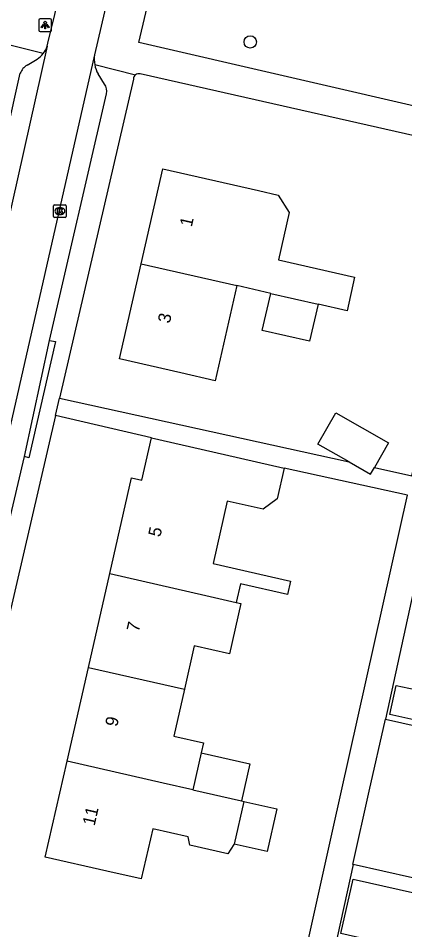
# Model space of a CAD drawing. Extents: x 163686 to 164493, y 382719 to 383870.
# Drawn here: x 164007.2 to 164037.9, y 383506.8 to 383579.1 of the extents above; entities that cross this region are included whole.
import ezdxf

# ---------------------------------------------------------------- set-up
doc = ezdxf.new("R2010")
doc.units = 0
for name, color, linetype in [('IMGEO_Boom', 7, 'Continuous'), ('IMGEO_Kolk', 7, 'Continuous'), ('IMGEO_Lichtpunt', 7, 'Continuous'), ('IMGEO_Pand', 7, 'Continuous'), ('IMGEO_Pand_nummerreeks', 7, 'Continuous'), ('IMGEO_Rijbaan_lokaal_open', 7, 'Continuous'), ('IMGEO_Voetpad_open', 7, 'Continuous')]:
    doc.layers.add(name, color=color, linetype=linetype)

msp = doc.modelspace()

# ---------------------------------------------------------------- linework, layer by layer
at = {"layer": 'IMGEO_Boom'}
msp.add_circle((164025.64, 383577.233), 0.489, dxfattribs=at)
at = {"layer": 'IMGEO_Kolk'}
for p, q in [((164010.039, 383563.39), (164010.039, 383564.242)), ((164010.114, 383564.316), (164010.966, 383564.316)), ((164010.527, 383564.096), (164010.552, 383564.096)), ((164011.04, 383564.242), (164011.04, 383563.39)), ((164010.966, 383563.316), (164010.114, 383563.316)), ((164010.55, 383563.536), (164010.525, 383563.536))]:
    msp.add_line(p, q, dxfattribs=at)
for points in [[(164010.039, 383563.39), (164010.039, 383564.242)], [(164010.114, 383564.316), (164010.966, 383564.316)], [(164010.36, 383564.016), (164010.483, 383564.016), (164010.483, 383563.865), (164010.613, 383564.016), (164010.777, 383564.016), (164010.631, 383563.865), (164010.784, 383563.616), (164010.632, 383563.616), (164010.547, 383563.78), (164010.483, 383563.713), (164010.483, 383563.616), (164010.36, 383563.616), (164010.36, 383564.016)], [(164011.04, 383564.242), (164011.04, 383563.39)], [(164010.966, 383563.316), (164010.114, 383563.316)]]:
    msp.add_lwpolyline(points, dxfattribs=at)
for centre, start, end in [((164010.116, 383564.24), 91.55205, 178.44795), ((164010.116, 383564.24), 91.55205, 178.44795), ((164010.964, 383564.24), 1.55205, 88.44795), ((164010.964, 383564.24), 1.55205, 88.44795), ((164010.116, 383563.392), 181.55205, 268.44795), ((164010.116, 383563.392), 181.55205, 268.44795), ((164010.964, 383563.392), 271.55205, 358.44795), ((164010.964, 383563.392), 271.55205, 358.44795)]:
    msp.add_arc(centre, 0.0765, start, end, dxfattribs=at)
for centre, major_axis, ratio, start_param, end_param in [((164010.526, 383563.816), (-0.387, 0.002), 0.722429, 4.712389, 7.853982), ((164010.551, 383563.816), (-0.39, 0.002), 0.717154, 1.570796, 4.712389)]:
    msp.add_ellipse(centre, major_axis=major_axis, ratio=ratio, start_param=start_param, end_param=end_param, dxfattribs=at)
at = {"layer": 'IMGEO_Lichtpunt'}
for p, q in [((164009.773, 383579.07), (164008.965, 383579.07)), ((164009.773, 383579.07), (164008.965, 383579.07)), ((164008.871, 383578.975), (164008.871, 383578.168)), ((164008.871, 383578.975), (164008.871, 383578.168)), ((164009.867, 383578.168), (164009.867, 383578.975)), ((164009.867, 383578.168), (164009.867, 383578.975)), ((164008.965, 383578.074), (164009.773, 383578.074)), ((164008.965, 383578.074), (164009.773, 383578.074))]:
    msp.add_line(p, q, dxfattribs=at)
for points in [[(164009.245, 383578.639), (164009.284, 383578.611), (164009.096, 383578.349), (164009.058, 383578.376), (164009.245, 383578.639)], [(164009.347, 383578.591), (164009.394, 383578.591), (164009.394, 383578.269), (164009.347, 383578.269), (164009.347, 383578.591)], [(164009.457, 383578.611), (164009.495, 383578.638), (164009.682, 383578.376), (164009.643, 383578.348), (164009.457, 383578.611)]]:
    msp.add_lwpolyline(points, dxfattribs=at)
msp.add_circle((164009.37, 383578.773), 0.0994, dxfattribs=at)
for centre, start, end in [((164008.965, 383578.975), 90, 180), ((164008.965, 383578.975), 90, 180), ((164009.773, 383578.975), 0, 90), ((164009.773, 383578.975), 0, 90), ((164008.965, 383578.168), 180, 270), ((164008.965, 383578.168), 180, 270), ((164009.773, 383578.168), 270, 0), ((164009.773, 383578.168), 270, 360)]:
    msp.add_arc(centre, 0.0946, start, end, dxfattribs=at)
at = {"layer": 'IMGEO_Pand'}
for points in [[(164016.977, 383559.63), (164018.692, 383567.171), (164026.298, 383565.442), (164027.858, 383565.087), (164028.725, 383563.711), (164027.871, 383559.957), (164033.922, 383558.581), (164033.315, 383555.914), (164031.019, 383556.437)], [(164024.583, 383557.902), (164022.867, 383550.363), (164020.139, 383550.983), (164015.263, 383552.092), (164016.977, 383559.63)], [(164016.977, 383559.63), (164024.583, 383557.902)], [(164027.265, 383557.291), (164024.583, 383557.902)], [(164031.019, 383556.437), (164030.347, 383553.485), (164026.593, 383554.338), (164027.265, 383557.291)], [(164027.265, 383557.291), (164031.019, 383556.437)], [(164033.477, 383543.915), (164031.01, 383545.325), (164032.439, 383547.825), (164036.61, 383545.441), (164035.485, 383543.472)], [(164014.486, 383535.057), (164016.217, 383542.668), (164017.046, 383542.48), (164017.807, 383545.825)], [(164017.807, 383545.825), (164022.683, 383544.716), (164028.338, 383543.43)], [(164033.477, 383543.915), (164035.181, 383542.941), (164035.485, 383543.472)], [(164028.338, 383543.43), (164027.785, 383540.993), (164026.675, 383540.169), (164023.816, 383540.818), (164022.686, 383535.847), (164028.824, 383534.451), (164028.583, 383533.39), (164024.856, 383534.237), (164024.523, 383532.776)], [(164012.794, 383527.617), (164014.486, 383535.057)], [(164014.486, 383535.057), (164022.112, 383533.324), (164024.523, 383532.776)], [(164024.523, 383532.776), (164024.899, 383532.69), (164023.989, 383528.683), (164021.201, 383529.317), (164020.42, 383525.884)], [(164011.102, 383520.176), (164012.794, 383527.617)], [(164012.794, 383527.617), (164020.42, 383525.884)], [(164020.42, 383525.884), (164019.574, 383522.163), (164021.928, 383521.628), (164021.748, 383520.836)], [(164039.09, 383523.36), (164036.707, 383523.889), (164037.218, 383526.19), (164038.714, 383525.858), (164039.391, 383524.715), (164039.09, 383523.36)], [(164033.805, 383511.988), (164033.781, 383511.993), (164035.085, 383517.792), (164036.373, 383523.522)], [(164036.373, 383523.522), (164044.622, 383521.668)], [(164021.748, 383520.836), (164021.082, 383517.908)], [(164021.748, 383520.836), (164025.615, 383519.957), (164024.949, 383517.029)], [(164024.358, 383513.599), (164024.348, 383513.555), (164023.858, 383512.836), (164020.855, 383513.519), (164020.724, 383514.17), (164017.902, 383514.812), (164016.997, 383510.833), (164014.248, 383511.458), (164009.372, 383512.567), (164011.102, 383520.176)], [(164021.082, 383517.908), (164018.728, 383518.443), (164011.102, 383520.176)], [(164044.012, 383518.95), (164044, 383518.896), (164039.771, 383519.846), (164038.677, 383514.979), (164041.749, 383514.288), (164040.875, 383510.399), (164033.805, 383511.988)], [(164021.082, 383517.908), (164024.949, 383517.029)], [(164025.128, 383516.988), (164027.748, 383516.392), (164026.978, 383513.004), (164024.358, 383513.599)], [(164025.128, 383516.988), (164024.358, 383513.599)], [(164024.949, 383517.029), (164025.128, 383516.988)], [(164042.291, 383495.9), (164038.483, 383496.766), (164039.487, 383501.181), (164045.932, 383499.715), (164045.997, 383500), (164046.662, 383502.927), (164040.647, 383504.295), (164040.727, 383504.716), (164032.829, 383506.5), (164033.806, 383510.81), (164044.764, 383508.37), (164049.644, 383507.284), (164049.387, 383506.153), (164054.798, 383504.922), (164053.966, 383501.265), (164054.141, 383501.225), (164053.863, 383500), (164052.988, 383496.145), (164051.866, 383496.4), (164051.33, 383494.04), (164052.451, 383493.785), (164052.409, 383493.6)]]:
    msp.add_lwpolyline(points, dxfattribs=at)
at = {"layer": 'IMGEO_Rijbaan_lokaal_open'}
for points in [[(164009.525, 383576.891), (164009.59, 383577.14), (164010.952, 383582.804)], [(164014.604, 383581.937), (164013.279, 383576.218)], [(164009.525, 383576.891), (164003.511, 383550.059), (163995.536, 383515.476)], [(164013.279, 383576.218), (163999.26, 383514.63)]]:
    msp.add_lwpolyline(points, dxfattribs=at)
at = {"layer": 'IMGEO_Voetpad_open'}
for points in [[(164019.56, 383587.035), (164045.236, 383581.166), (164045.758, 383580.337), (164043.752, 383571.528), (164043.093, 383571.179), (164040.731, 383571.663), (164016.807, 383577.196)], [(164016.807, 383577.196), (164019.015, 383586.644)], [(164009.22, 383576.32), (164006.36, 383577.041)], [(164007.934, 383575.39), (164008.744, 383575.88)], [(164013.303, 383575.434), (164016.53, 383574.628)], [(164003.013, 383555.196), (164007.389, 383574.75)], [(164014.081, 383573.896), (164013.569, 383574.697)], [(164072.003, 383562.118), (164045.437, 383568.257), (164016.902, 383574.697)], [(164016.375, 383574.283), (164010.501, 383548.981)], [(164009.716, 383553.561), (164014.227, 383573.127)], [(164035.485, 383543.472), (164038.456, 383542.817), (164041.21, 383554.506), (164042.305, 383554.248), (164043.082, 383554.065), (164039.552, 383538.055), (164036.373, 383523.522)], [(164007.738, 383544.342), (164009.716, 383553.561)], [(164009.716, 383553.561), (164010.201, 383553.478), (164008.076, 383544.252), (164007.738, 383544.342)], [(164010.179, 383547.596), (164010.501, 383548.981)], [(164010.501, 383548.981), (164033.477, 383543.915)], [(164010.179, 383547.596), (164003.126, 383517.221), (163992.708, 383471.874), (163988.857, 383454.418), (163980.269, 383406.063)], [(164017.807, 383545.825), (164010.179, 383547.596)], [(164001.385, 383516.969), (164003.14, 383524.826), (164007.738, 383544.342)], [(164028.068, 383496.176), (164032.229, 383514.859), (164038.113, 383541.275), (164028.338, 383543.43)], [(164033.805, 383511.988), (164030.829, 383498.491)]]:
    msp.add_lwpolyline(points, dxfattribs=at)
for centre, radius, start, end in [((164007.648, 383577.526), 1.981, 322.48876, 341.29338), ((164007.666, 383577.524), 1.966, 303.25854, 322.24018), ((164015.754, 383575.901), 2.495, 172.70968, 190.79713), ((164015.762, 383575.905), 2.504, 190.84287, 208.84845), ((164008.558, 383574.306), 1.251, 119.94972, 159.21734), ((164016.782, 383574.304), 0.41, 73.0618, 127.95425), ((164016.78, 383574.308), 0.406, 128.03032, 183.58326), ((164013.367, 383573.362), 0.891, 344.70522, 36.79489)]:
    msp.add_arc(centre, radius, start, end, dxfattribs=at)

# ---------------------------------------------------------------- texts
at = {"layer": 'IMGEO_Pand_nummerreeks'}
for s, rotation, p in [('1', 77.18867, (164020.998, 383562.516)), ('3', 77.18867, (164019.257, 383554.866)), ('5', 77.18887, (164018.499, 383537.909)), ('7', 77.18887, (164016.788, 383530.384)), ('9', 77.18887, (164015.077, 383522.859)), ('11', 77.18887, (164013.288, 383514.997))]:
    msp.add_text(s, height=1, rotation=rotation, dxfattribs=at).set_placement(p)

doc.saveas('drawing.dxf')
